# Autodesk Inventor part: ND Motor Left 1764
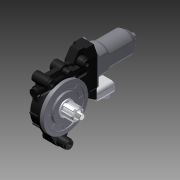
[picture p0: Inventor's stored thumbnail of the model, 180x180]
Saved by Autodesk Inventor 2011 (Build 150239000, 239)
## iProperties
Shininess: 64.0
Length Units: 11269
Angle Units: 11279
Time Units: 11290
Mass Units: 11283
Length Display Precision: 3
Angle Display Precision: 2
Compacted: True
Part Number: ND Motor Left 1764
Document SubType Name: Modeling
Created: 2006-01
Material: ABS Plastic
Designer: uidk0133
Density: 1.06 g/cm^3
Density: 0.0
Volumn: 0.0
Area: 0.0
PropertySet Name: Model Information
Control State: 0
Master: False
Checked Out: False
Author: uidk0133
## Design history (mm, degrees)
sketch "Sketch1"
  geometry: C1 r 36 at (0, 0); 1 further point
  constraints: 1 centre point, 1 coincident, 1 other
  dimensions: "d0" = 72 diameter of C1
extrude "Extrusion1" new body sketch "Sketch1" distance "d1" = 5.8; taper "d2" = 0 deg
sketch "Sketch2"
  geometry: C1 r 36 at (0, 0) reference; C2 r 30 at (0, 0); C3 r 21 at (0, 0)
  constraints: 2 centre point, 2 coincident, 2 concentric
  dimensions: "d3" = 60 diameter of C2; "d4" = 42 diameter of C3
extrude "Extrusion2" cut sketch "Sketch2" distance "d5" = 2; taper "d6" = 0 deg
sketch "Sketch3"
  geometry: C1 r 21 at (0, 0) reference; C2 r 23 at (0, 0); C3 r 21 at (0, 0) reference
  constraints: 1 centre point, 1 concentric
  dimensions: "d7" = 2 radial gap between concentric circles of C2 C1
extrude "Extrusion3" cut sketch "Sketch3" distance "d8" = 1; taper "d9" = 0 deg
sketch "Sketch4"
  geometry: C1 r 21 at (0, 0) reference; C2 r 13 at (0, 0)
  constraints: 1 centre point, 1 coincident, 1 concentric
  dimensions: "d10" = 26 diameter of C2
extrude "Extrusion4" join sketch "Sketch4" distance "d11" = 0.5; taper "d12" = 0 deg
sketch "Sketch5"
  geometry: L1 (0, 30)-(0, 30); L2 (2, 28)-(2, 24); L3 (0, 22)-(0, 22); L4 (-2, 24)-(-2, 28); L5 (0, 0)-(0, 27.01); C1 r 21 at (0, 0) reference; C2 r 23 at (0, 0) reference; A1 r 2 centre (0, 24) between (-2, 24) and (0, 22); A2 r 2 centre (0, 24) between (0, 22) and (2, 24); A3 r 2 centre (0, 28) between (0, 30) and (-2, 28); A4 r 2 centre (0, 28) between (2, 28) and (0, 30); 4 further points
  constraints: 10 end point, 8 point on circle, 8 point on line, 8 tangent, 4 centre point, 3 parallel, 2 concentric, 1 equal radius, 1 horizontal, 1 perpendicular, 1 other
  dimensions: "d13" = 4 distance of point (2, 22) point (-2, 22); "d14" = 8 distance of point (2, 30) point (2, 22); "d15" = 22 vertical distance of C1.centre point (2, 22); "d18" = 2 radius of A1
extrude "Extrusion5" join sketch "Sketch5" distance "d16" = 1.5; taper "d17" = 0 deg
pattern_circular "Circular Pattern1" dims angle "d21" = 360 deg
sketch "Sketch6"
  geometry: C1 r 13 at (0, 0) reference; C2 r 11.95 at (0, 0)
  constraints: 1 centre point, 1 coincident, 1 concentric
  dimensions: "d22" = 23.9 diameter of C2
extrude "Extrusion6" join sketch "Sketch6" distance "d23" = 1.7; taper "d24" = 0 deg
sketch "Sketch7"
  geometry: C1 r 11.95 at (0, 0) reference; C2 r 8.1 at (0, 0)
  constraints: 1 centre point, 1 coincident, 1 concentric
  dimensions: "d25" = 16.2 diameter of C2
extrude "Extrusion7" join sketch "Sketch7" distance "d26" = 17.9; taper "d27" = 0 deg
sketch "Sketch8"
  geometry: C1 r 8.1 at (0, 0) reference; 1 further point
  constraints: 1 coincident
hole "Hole1" sketch "Sketch8" at (0, 0) diameter "d28" = 13; stored, may be unused: countersink angle "d32" = 82 deg, drill point angle "d34" = 0 deg; dims "d29" = 6, "d30" = 4, "d31" = 2, "d33" = 2
sketch "Sketch9"
  geometry: L1 (-2, -7.849)-(2, -7.849); L2 (2, -7.849)-(2, -10); L3 (2, -10)-(-2, -10); L4 (-2, -10)-(-2, -7.849); L5 (0, 0)-(0, 8.1); C1 r 11.95 at (0, 0) reference; A1 r 8.1 centre (0, 0) between (-2, -7.849) and (0, 8.1) reference
  constraints: 10 end point, 3 parallel, 2 point on circle, 1 horizontal, 1 perpendicular, 1 other
  dimensions: "d35" = 4 distance of L2.end L3.end; "d36" = 10 distance from line of L3 A1.centre
extrude "Extrusion8" join sketch "Sketch9" distance "d37" = 18; taper "d38" = 0 deg
chamfer "Chamfer1" distance "d39" = 2; stored, may be unused: second distance "d40" = 2, angle "d354" = 45 deg
pattern_circular "Circular Pattern2" dims angle "d43" = 360 deg
sketch "Sketch10"
  geometry: C1 r 6.5 at (0, 0) reference; C2 r 6.25 at (0, 0)
  constraints: 1 centre point, 1 coincident, 1 concentric
  dimensions: "d44" = 12.5 diameter of C2
extrude "Extrusion9" join sketch "Sketch10" distance "d45" = 0.2; taper "d46" = 0 deg
sketch "Sketch11"
  geometry: C1 r 6.25 at (0, 0) reference; C2 r 4 at (0, 0)
  constraints: 1 centre point, 1 coincident, 1 concentric
  dimensions: "d47" = 8 diameter of C2
extrude "Extrusion10" join sketch "Sketch11" distance "d48" = 8.2; taper "d49" = 0 deg
chamfer "Chamfer2" distance "d50" = 0.5; stored, may be unused: second distance "d51" = 2, angle "d355" = 45 deg
fillet "Fillet1" dims "d52" = 0.5
fillet "Fillet2" dims "d53" = 1.5
sketch "Sketch12"
  geometry: C1 r 36 at (0, 0) reference; C2 r 35.5 at (0, 0)
  constraints: 1 centre point, 1 coincident, 1 concentric
  dimensions: "d54" = 71 diameter of C2
extrude "Extrusion11" join sketch "Sketch12" distance "d55" = 0.5; taper "d56" = 0 deg
sketch "Sketch13"
  geometry: C1 r 36 at (0, 0) reference
extrude "Extrusion12" join sketch "Sketch13" distance "d57" = 3; taper "d58" = 0 deg
sketch "Sketch14"
  geometry: C1 r 36 at (0, 0) reference; C2 r 34 at (0, 0)
  constraints: 1 centre point, 1 coincident, 1 concentric
  dimensions: "d59" = 68 diameter of C2
extrude "Extrusion13" join sketch "Sketch14" distance "d60" = 14; taper "d61" = 0 deg
sketch "Sketch15"
  geometry: L1 (34, -17.5)-(-34, -17.5) reference; L2 (0, -17.5)-(0, -21); L3 (0, -21)-(-10, -21); L4 (-10, -21)-(-32, -17.5)
  constraints: 6 end point, 2 perpendicular, 1 midpoint, 1 point on line
  dimensions: "d62" = 2 distance of L1.end L4.end; "d63" = 3.5 distance of L2.start L2.end; "d64" = 10 distance of L2.end L3.end
revolve "Revolution1" sketch "Sketch15" stored, may be unused: angle "d65" = 90 deg
sketch "Sketch16"
  geometry: L1 (0, 0)-(0, 40.089); L2 (0, 0)-(19.504, 33.782); L3 (1, 9.95)-(1, 31.984); L4 (4.109, 9.117)-(15.126, 28.199); A1 r 10 centre (0, 0) between (1, 9.95) and (4.109, 9.117) reference; A2 r 10 centre (0, 0) between (4.109, 9.117) and (1, 9.95); A3 r 32 centre (0, 0) between (15.126, 28.199) and (1, 31.984); 1 further point
  constraints: 8 end point, 6 point on circle, 2 centre point, 2 coincident, 2 parallel, 1 vertical, 2 other
  dimensions: "d66" = 30 deg angle of L2 L1; "d67" = 1 distance between parallel lines of L1 L3; "d68" = 1 distance between parallel lines of L2 L4
extrude "Extrusion14" cut sketch "Sketch16" distance "d69" = 4.5; taper "d70" = 0 deg
pattern_circular "Circular Pattern3" dims angle "d73" = 360 deg
sketch "Sketch17"
  geometry: C1 r 10 at (0, 0); A1 r 10 centre (0, 0) between (4.109, 9.117) and (1, 9.95) reference; A2 r 10 centre (0, 0) between (8.117, 5.841) and (5.841, 8.117) reference
  constraints: 2 concentric, 1 centre point, 1 coincident
extrude "Extrusion15" join sketch "Sketch17" distance "d74" = 0.5; taper "d75" = 0 deg
fillet "Fillet3" dims "d76" = 0.5
sketch "Sketch18"
  geometry: C1 r 19.5 at (1, -9.95); C2 r 21.5 at (1, -9.95); A1 r 10 centre (1, -9.95) between (0, 0) and (-3.109, -0.833) reference
  constraints: 2 centre point, 1 coincident, 1 concentric
  dimensions: "d77" = 43 diameter of C2; "d78" = 2 radial gap between concentric circles of C1 C2
extrude "Extrusion16" join sketch "Sketch18" distance "d79" = 2; taper "d80" = 0 deg
fillet "Fillet4" dims "d81" = 1
sketch "Sketch19"
  geometry: C1 r 9.5 at (0, 0) reference; 1 further point
  constraints: 1 coincident
hole "Hole2" sketch "Sketch19" at (0, 0) diameter "d82" = 2.6; stored, may be unused: countersink angle "d86" = 82 deg, drill point angle "d88" = 0 deg; dims "d83" = 6, "d84" = 4, "d85" = 2, "d87" = 8
sketch "Sketch21"
  geometry: L1 (-1, 33.985)-(1, 33.985); L2 (1, 33.985)-(1, 35.985); L3 (1, 35.985)-(-1, 35.985); L4 (-1, 35.985)-(-1, 33.985); L5 (-1, 21.477)-(-1, 31.921) reference; L6 (1, 31.921)-(1, 21.477) reference; 1 further point
  constraints: 8 end point, 2 collinear, 2 parallel, 1 horizontal, 1 perpendicular, 2 other
  dimensions: "d93" = 2 distance of L1.end L2.end
extrude "Extrusion18" join sketch "Sketch21" distance "d94" = 15.5; taper "d95" = 0 deg
fillet "Fillet5" dims "d96" = 0.9
pattern_circular "Circular Pattern4" dims angle "d99" = 360 deg
workplane "Work Plane1"
workplane "Work Plane2"
workaxis "Work Axis1"
sketch "Sketch22"
  geometry: L1 (-57.6, -6.2)-(43.2, -6.2) reference; L2 (33.88, -27.93)-(33.88, 48.09) reference; C1 r 7.5 at (33.88, -6.2); 1 further point
  constraints: 2 point on line, 1 centre point, 1 coincident
  dimensions: "d102" = 15 diameter of C1
extrude "Extrusion19" join sketch "Sketch22" distance "d103" = 35; taper "d104" = 0 deg
sketch "Sketch23"
  geometry: C1 r 7.5 at (-33.88, 6.2); 10 further points
  constraints: 1 centre point, 1 coincident, 3 other
extrude "Extrusion20" join sketch "Sketch23" distance "d105" = 20; taper "d106" = 0 deg
sketch "Sketch24"
  geometry: C1 r 11.5 at (-33.88, 6.2); 3 further points
  constraints: 1 centre point, 1 coincident, 2 other
  dimensions: "d110" = 23 diameter of C1
extrude "Extrusion21" join sketch "Sketch24" distance "d108" = 14.5; taper "d109" = 0 deg
sketch "Sketch25"
  geometry: C1 r 7.5 at (0, 0) reference; C2 r 6.125 at (0, 0)
  constraints: 1 centre point, 1 coincident, 1 concentric
  dimensions: "d111" = 12.25 diameter of C2
extrude "Extrusion22" join sketch "Sketch25" distance "d112" = 5; taper "d113" = 0 deg
sketch "Sketch26"
  geometry: L1 (-30, -15.5)-(30, -15.5); L2 (30, -15.5)-(30, 15.5); L3 (30, 15.5)-(-30, 15.5); L4 (-30, 15.5)-(-30, -15.5); L5 (0, 0)-(0, 15.5); L6 (0, 0)-(0, -15.5); L7 (0, 0)-(-30, 0); L8 (0, 0)-(30, 0); C1 r 11.5 at (0, 0) reference
  constraints: 16 end point, 4 midpoint, 4 perpendicular, 3 parallel, 2 collinear, 1 coincident, 1 horizontal, 1 other
  dimensions: "d114" = 60 distance of L2.end L3.end; "d115" = 31 distance of L3.end L1.start
extrude "Extrusion23" join sketch "Sketch26" distance "d116" = 12.5; taper "d117" = 0 deg
fillet "Fillet6" dims "d118" = 4
chamfer "Chamfer3" distance "d119" = 12; stored, may be unused: second distance "d120" = 6, angle "d356" = 45 deg
chamfer "Chamfer4" distance "d121" = 6; stored, may be unused: second distance "d122" = 12, angle "d357" = 45 deg
sketch "Sketch27"
  geometry: L1 (30, 9.5)-(30, -9.5) reference; L2 (18, 15.5)-(30, 9.5) reference; L3 (-26, 15.5)-(18, 15.5) reference; L4 (-30, -11.5)-(-30, 11.5) reference; L5 (18, -15.5)-(-26, -15.5) reference; L6 (30, -9.5)-(18, -15.5) reference; L7 (30, 9.5)-(30, -9.5) reference; L8 (18, 15.5)-(30, 9.5) reference; L9 (17.953, 15.3)-(-26, 15.3); L10 (-29.8, 11.5)-(-29.8, -11.5); L11 (-26, -15.3)-(17.953, -15.3); L12 (17.953, -15.3)-(29.8, -9.376); L13 (29.8, -9.376)-(29.8, -3.693); L14 (23.588, -0.107)-(29.8, -3.693); L15 (30, -9.5)-(18, -15.5) reference; A1 r 4 centre (-26, 11.5) between (-26, 15.5) and (-30, 11.5) reference; A2 r 4 centre (-26, -11.5) between (-30, -11.5) and (-26, -15.5) reference; A3 r 3.8 centre (-26, 11.5) between (-26, 15.3) and (-29.8, 11.5); A4 r 3.8 centre (-26, -11.5) between (-29.8, -11.5) and (-26, -15.3); A5 r 23.588 centre (0, 0) between (23.588, -0.107) and (17.953, 15.3); 1 further point
  constraints: 12 end point, 6 point on circle, 3 centre point, 1 coincident, 1 parallel, 1 other
  dimensions: "d327" = 120 deg angle of L13 L14; "d328" = 0.2 distance between parallel lines of L3 L9; "d329" = 0.2 distance between parallel lines of L15 L12; "d330" = 0.2 distance between parallel lines of L1 L13
extrude "Extrusion24" join sketch "Sketch27" distance "d127" = 2; taper "d128" = 0 deg
fillet "Fillet7" dims "d129" = 1
sketch "Sketch28"
  geometry: L1 (-26, 15.3)-(17.485, 15.3) reference; L2 (17.717, -15.3)-(-26, -15.3) reference; L3 (-12.881, 15.3)-(12.881, 15.3); L4 (-12.881, -15.3)-(12.881, -15.3); A1 r 20 centre (0, 0) between (-12.881, 15.3) and (-12.881, -15.3); A2 r 20 centre (0, 0) between (12.881, -15.3) and (12.881, 15.3); 1 further point
  constraints: 4 end point, 4 point on circle, 4 point on line, 2 centre point, 1 coincident, 1 collinear, 1 concentric, 1 parallel, 1 other
  dimensions: "d332" = 20 radius of A2
extrude "Extrusion25" join sketch "Sketch28" distance "d131" = 15; taper "d132" = 0 deg
sketch "Sketch29"
  geometry: L1 (-12.881, -15.3)-(-12.881, -15.3) reference; L2 (-12.881, 15.3)-(-12.881, 15.3) reference; L3 (12.881, -15.3)-(-12.881, -15.3) reference; L4 (-12.881, 15.3)-(12.881, 15.3) reference; L5 (8.495, -15.3)-(-8.495, -15.3); L6 (8.495, 15.3)-(-8.495, 15.3); A1 r 17.5 centre (0, 0) between (8.495, -15.3) and (8.495, 15.3); A2 r 17.5 centre (0, 0) between (-8.495, 15.3) and (-8.495, -15.3); 1 further point
  constraints: 4 end point, 4 point on circle, 4 point on line, 2 centre point, 1 coincident, 1 concentric, 1 other
  dimensions: "d334" = 17.5 radius of A2
extrude "Extrusion26" join sketch "Sketch29" distance "d135" = 40; taper "d136" = 0 deg
chamfer "Chamfer5" distance "d137" = 2.5; stored, may be unused: second distance "d138" = 12, angle "d358" = 45 deg
chamfer "Chamfer6" distance "d139" = 1; stored, may be unused: second distance "d140" = 12, angle "d359" = 45 deg
fillet "Fillet8" dims "d143" = 4
sketch "Sketch31"
  geometry: L1 (-7.386, -15.3)-(7.386, -15.3); L2 (7.386, 15.3)-(-7.386, 15.3) reference; A1 r 4 centre (7.386, -11.3) between (7.386, -15.3) and (9.575, -14.648); A2 r 4 centre (-7.386, -11.3) between (-9.575, -14.648) and (-7.386, -15.3); A3 r 17.5 centre (0, 0) between (-9.575, -14.648) and (9.575, -14.648); A4 r 4 centre (7.386, 11.3) between (9.575, 14.648) and (7.386, 15.3) reference; A5 r 17.5 centre (0, 0) between (9.575, 14.648) and (-9.575, 14.648) reference; A6 r 4 centre (-7.386, 11.3) between (-7.386, 15.3) and (-9.575, 14.648) reference
  constraints: 6 point on circle, 3 centre point, 2 end point
extrude "Extrusion27" cut sketch "Sketch31" stored distance "d145" = 43; taper "d146" = 0 deg
mirror "Mirror1"
sketch "Sketch32"
  geometry: C1 r 9.896 at (0, 0); C2 r 5 at (0, 0); C3 r 12 at (0, 0) reference
  constraints: 2 centre point, 1 coincident, 1 concentric
  dimensions: "d150" = 10 diameter of C2
extrude "Extrusion28" join sketch "Sketch32" distance "d151" = 4; taper "d152" = 0 deg
sketch "Sketch33"
  geometry: C1 r 5 at (0, 0) reference; C2 r 4.5 at (0, 0)
  constraints: 1 centre point, 1 coincident, 1 concentric
  dimensions: "d153" = 9 diameter of C2
extrude "Extrusion29" join sketch "Sketch33" distance "d154" = 5; taper "d155" = 0 deg
fillet "Fillet10" dims "d156" = 1, "d157" = 0.5
sketch "Sketch35"
  geometry: L1 (-22.38, 25.596)-(-22.38, 34.5) reference; L2 (-3.88, 34.5)-(-7.88, 34.5) reference; L3 (-22.38, 25.596)-(-22.38, 34.5); L4 (-3.88, 34.5)-(-3.88, 33.778); L5 (-7.88, 34.5)-(-22.38, 34.5); A1 r 34 centre (0, 0) between (-0.1, 34) and (-16.913, 29.495) reference; A2 r 34 centre (0, 0) between (-17.087, 29.395) and (-29.395, 17.087) reference; A3 r 34 centre (0, 0) between (-3.88, 33.778) and (-22.38, 25.596); 3 further points
  constraints: 6 end point, 3 point on circle, 1 centre point, 1 coincident, 1 collinear, 1 parallel, 1 perpendicular
extrude "Extrusion30" join sketch "Sketch35" stored distance "d158" = 2; taper "d159" = 0 deg
sketch "Sketch36"
  geometry: L1 (-30, -9.5)-(-30, 9.5); L2 (-30, 6.6)-(0, 6.6); L3 (0, 6.6)-(0, -6.6); L4 (0, -6.6)-(-30, -6.6); L5 (-30, -6.6)-(-30, 6.6); L6 (0, 0)-(-24.292, 0); L7 (30, -1)-(11.5, -1) reference; L8 (11.5, -1)-(11.5, 0) reference; L9 (11.5, 0)-(11.5, 1) reference; L10 (11.5, 1)-(30, 1) reference; L11 (30, 2.7)-(30, 1) reference; L12 (23.597, 2.7)-(30, 2.7) reference; L13 (23.597, 5.7)-(23.597, 2.7) reference; L14 (25.513, 5.7)-(23.597, 5.7) reference; L15 (25.513, 6.2)-(25.513, 5.7) reference; L16 (23.597, 6.2)-(25.513, 6.2) reference; L17 (23.597, 11.5)-(23.597, 6.2) reference; L18 (30, 12)-(25.513, 12) reference; L19 (30, 15.5)-(30, 12) reference; L20 (23.717, 15.5)-(30, 15.5) reference; L21 (-30, -11.5)-(-30, 11.5) reference; L22 (18, -15.5)-(-26, -15.5) reference; L23 (30, -9.5)-(18, -15.5) reference; L24 (30, -1)-(30, -9.5) reference; C1 r 11.5 at (0, 0); C2 r 11.5 at (0, 0) reference; A1 r 4 centre (-26, 11.5) between (-26, 15.5) and (-30, 11.5) reference; A2 r 4 centre (-26, -11.5) between (-30, -11.5) and (-26, -15.5) reference
  constraints: 12 end point, 2 parallel, 2 perpendicular, 1 centre point, 1 horizontal, 1 point on line, 2 other
  dimensions: "d160" = 13.2 distance of L2.end L3.end; "d161" = 30 distance of L3.end L4.end
extrude "Extrusion31" join sketch "Sketch36" distance "d162" = 18; taper "d163" = 0 deg
chamfer "Chamfer8" distance "d164" = 9; stored, may be unused: second distance "d165" = 14, angle "d360" = 45 deg
sketch "Sketch37"
  geometry: L1 (-16, -6.6)-(-16, 6.6) reference; L2 (-6.537, 3.677)-(-16, 3.677); L3 (-16, 3.677)-(-16, -3.323); L4 (-16, -3.323)-(-6.537, -3.323); L5 (-6.537, -3.323)-(-6.537, 3.677); L6 (-1.408, 0)-(-40.663, 0); A1 r 7.5 centre (0, 0) between (-3.562, 6.6) and (-3.562, -6.6) reference; A2 r 7.333 centre (0, 0) between (-6.391, 3.595) and (-6.537, -3.323); 1 further point
  constraints: 10 end point, 3 point on circle, 2 coincident, 2 parallel, 2 perpendicular, 1 centre point, 1 collinear, 1 horizontal, 1 other
  dimensions: "d166" = 7 distance of L2.end L3.end
extrude "Extrusion32" join sketch "Sketch37" distance "d167" = 50; taper "d168" = 0 deg
sketch "Sketch38"
  geometry: L1 (59.3, -14.5)-(54.081, -14.5); L2 (5.917, 14.5)-(0.7, 14.5) reference; L3 (0, 0)-(0, -9) reference; C1 r 7 at (14.88, -6.21)
  constraints: 2 end point, 1 centre point
  dimensions: "d170" = 14 diameter of C1; "d337" = 20.71 distance from line of C1.centre L2; "d353" = 14.88 distance from line of C1.centre L3
extrude "Extrusion33" join sketch "Sketch38" distance "d172" = 8.2; taper "d173" = 0 deg
sketch "Sketch39"
  geometry: C1 r 6.15 at (14.88, -6.21); A1 r 7 centre (14.88, -6.21) between (11.65, 0) and (18.11, 0) reference
  constraints: 1 centre point, 1 coincident, 1 concentric
  dimensions: "d174" = 12.3 diameter of C1
extrude "Extrusion34" join sketch "Sketch39" distance "d175" = 3; taper "d176" = 0 deg
sketch "Sketch40"
  geometry: C1 r 6.15 at (0, 0) reference; 1 further point
  constraints: 1 coincident
hole "Hole3" sketch "Sketch40" at (0, 0) diameter "d177" = 4.8; stored, may be unused: countersink angle "d181" = 82 deg, drill point angle "d183" = 0 deg; dims "d178" = 6, "d179" = 6.2, "d180" = 2, "d182" = 8
sketch "Sketch41"
  geometry: L1 (-26.38, -35)-(-41.38, -35) reference; L2 (-26.38, -21.45)-(-26.38, -35) reference; L3 (-26.38, -35)-(-22.38, -35); L4 (-22.38, -35)-(-17.481, -29.162); L5 (-26.38, -21.45)-(-26.38, -35); A1 r 34 centre (0, 0) between (-16.913, -29.495) and (-0.1, -34) reference; A2 r 34 centre (0, 0) between (-29.395, -17.087) and (-17.087, -29.395) reference; A3 r 34 centre (0, 0) between (-26.38, -21.45) and (-17.481, -29.162); 1 further point
  constraints: 6 end point, 3 point on circle, 1 centre point, 1 coincident, 1 collinear, 1 perpendicular
  dimensions: "d314" = 4 distance of L2.end L3.end; "d315" = 130 deg angle of L3 L4
extrude "Extrusion35" join sketch "Sketch41" stored distance "d186" = 2; taper "d187" = 0 deg
sketch "Sketch43"
  geometry: L1 (-22.38, -35)-(-18.526, -30.407) reference; L2 (-15.704, -30.156)-(-21.447, -37); L3 (-21.447, -37)-(-33.88, -37); L4 (-22.38, -35)-(-17.481, -29.162); L5 (-22.38, -35)-(-33.88, -35); L6 (-26.38, -35)-(-41.38, -35) reference; L7 (-33.88, -35)-(-33.88, -37); L8 (-33.88, -35)-(-33.88, -37); A1 r 34 centre (0, 0) between (-16.913, -29.495) and (-0.1, -34) reference; A2 r 34 centre (0, 0) between (-29.395, -17.087) and (-17.087, -29.395) reference; A3 r 34 centre (0, 0) between (-17.087, -29.395) and (-15.704, -30.156); 1 further point
  constraints: 12 end point, 4 point on circle, 1 centre point, 1 coincident, 1 collinear, 1 midpoint, 1 parallel, 1 perpendicular, 1 point on line
  dimensions: "d317" = 2 distance between parallel lines of L2 L1; "d318" = 2 distance from line of L3 L6.start
extrude "Extrusion36" join sketch "Sketch43" stored distance "d191" = 7; taper "d192" = 0 deg
sketch "Sketch46"
  geometry: L1 (-43.896, 112)-(-24.104, 112) reference; C1 r 7 at (-49, -28.29); C2 r 3.1 at (-49, 28.29) reference; A1 r 7 centre (-49, 28.29) between (-52.23, 34.5) and (-45.77, 34.5) reference
  constraints: 1 centre point, 1 equal radius, 1 vertical alignment
  dimensions: "d320" = 56.58 distance of C1.centre A1.centre
extrude "Extrusion39" join sketch "Sketch46" distance "d200" = 14.8; taper "d201" = 0 deg
sketch "Sketch47"
  geometry: C1 r 7 at (0, 0) reference; C2 r 6.15 at (0, 0)
  constraints: 1 centre point, 1 coincident, 1 concentric
  dimensions: "d202" = 12.3 diameter of C2
extrude "Extrusion40" join sketch "Sketch47" distance "d203" = 3; taper "d204" = 0 deg
sketch "Sketch48"
  geometry: C1 r 7 at (49, -28.29); 3 further points
  constraints: 1 centre point, 1 coincident, 2 other
extrude "Extrusion41" join sketch "Sketch48" distance "d205" = 8; taper "d206" = 0 deg
sketch "Sketch49"
  geometry: C1 r 6.15 at (0, 0) reference; 1 further point
  constraints: 1 coincident
hole "Hole4" sketch "Sketch49" at (0, 0) diameter "d207" = 4.8; stored, may be unused: countersink angle "d211" = 82 deg, drill point angle "d213" = 0 deg; dims "d208" = 6, "d209" = 6.2, "d210" = 2, "d212" = 8
sketch "Sketch50"
  geometry: L1 (0, 0)-(0, 38.5); L2 (0, 0)-(0, -37.846) reference; L3 (33.485, 30.5)-(-10, 30.5) reference; C1 r 7.75 at (5, -10.5)
  constraints: 2 end point, 1 centre point
  dimensions: "d214" = 15.5 diameter of C1; "d321" = 41 distance from line of L3 C1.centre; "d322" = 5 distance from line of L2 C1.centre
extrude "Extrusion42" join sketch "Sketch50" distance "d217" = 16; taper "d218" = 0 deg
sketch "Sketch51"
  geometry: L1 (10.116, 18)-(9.271, -14.855); L2 (0, 0)-(0, -4.579) reference; L3 (5.861, -14.662)-(9.457, -14.866); L4 (3.213, -6.644)-(4.612, 18); L5 (9.457, -14.866)-(9.47, 18); L6 (6.582, 18)-(27.5, 18) reference; L7 (4.11, 18)-(6.582, 18) reference; L8 (9.47, 18)-(4.11, 18); A1 r 7.75 centre (5, -10.5) between (0, -4.579) and (0, -16.421) reference; A2 r 4.25 centre (5, -10.5) between (3.213, -6.644) and (5.861, -14.662); 1 further point
  constraints: 10 end point, 5 point on line, 2 point on circle, 1 centre point, 1 coincident, 1 collinear, 1 concentric, 1 perpendicular
  dimensions: "d324" = 3.5 radial gap between concentric circles of A1 A2
extrude "Extrusion43" join sketch "Sketch51" distance "d222" = 9.5; taper "d223" = 0 deg
sketch "Sketch54"
  geometry: C1 r 7.1 at (48.4, 0); 1 further point
  constraints: 1 centre point, 1 horizontal alignment, 1 other
  dimensions: "d230" = 14.2 diameter of C1; "d231" = 48.4 distance of C1.centre point (0, 0)
extrude "Extrusion46" join sketch "Sketch54" distance "d232" = 14.8; taper "d233" = 0 deg
sketch "Sketch55"
  geometry: C1 r 7.1 at (0, 0) reference; C2 r 6.15 at (0, 0)
  constraints: 1 centre point, 1 coincident, 1 concentric
  dimensions: "d234" = 12.3 diameter of C2
extrude "Extrusion47" join sketch "Sketch55" distance "d235" = 3; taper "d236" = 0 deg
sketch "Sketch56"
  geometry: C1 r 7.1 at (0, 0) reference; C2 r 8.25 at (0, 0)
  constraints: 1 centre point, 1 coincident, 1 concentric
  dimensions: "d237" = 16.5 diameter of C2
extrude "Extrusion48" join sketch "Sketch56" distance "d238" = 17.5; taper "d239" = 0 deg
sketch "Sketch57"
  geometry: C1 r 6.15 at (0, 0) reference; 1 further point
  constraints: 1 coincident
hole "Hole5" sketch "Sketch57" at (0, 0) diameter "d240" = 4.8; stored, may be unused: countersink angle "d244" = 82 deg, drill point angle "d246" = 118 deg; dims "d241" = 6, "d242" = 6.2, "d243" = 2, "d245" = 28
sketch "Sketch58"
  geometry: C1 r 8.25 at (0, 0) reference; 1 further point
  constraints: 1 coincident
hole "Hole6" sketch "Sketch58" at (0, 0) diameter "d247" = 4.134; stored, may be unused: countersink angle "d251" = 82 deg, drill point angle "d253" = 0 deg; dims "d248" = 6, "d249" = 4.9, "d250" = 2, "d252" = 8
sketch "Sketch60"
  geometry: L1 (-31.114, -18.079)-(-31.214, -17.906) reference; L2 (-30.885, -16.677)-(-29.932, -16.127) reference; L3 (-33.985, -1)-(-35.085, -1) reference; L4 (-35.985, -0.1)-(-35.985, 0.1) reference; L5 (-35.085, 1)-(-33.985, 1) reference; L6 (-29.932, 16.127)-(-30.885, 16.677) reference; L7 (-31.214, 17.906)-(-31.114, 18.079) reference; L8 (-28.932, 17.859)-(-29.885, 18.409) reference; L9 (-29.885, -18.409)-(-28.932, -17.859) reference; L10 (-30.749, 18.428)-(-52.193, 7.326); L11 (-52.193, -7.326)-(-30.749, -18.428); L12 (-28.932, -17.859)-(-29.885, -18.409); A1 r 0.9 centre (-30.335, -17.629) between (-31.114, -18.079) and (-29.885, -18.409) reference; A2 r 0.9 centre (-30.435, -17.456) between (-30.885, -16.677) and (-31.214, -17.906) reference; A3 r 34 centre (0, 0) between (-33.985, -1) and (-29.932, -16.127) reference; A4 r 0.9 centre (-35.085, -0.1) between (-35.985, -0.1) and (-35.085, -1) reference; A5 r 0.9 centre (-35.085, 0.1) between (-35.085, 1) and (-35.985, 0.1) reference; A6 r 34 centre (0, 0) between (-29.932, 16.127) and (-33.985, 1) reference; A7 r 0.9 centre (-30.435, 17.456) between (-31.214, 17.906) and (-30.885, 16.677) reference; A8 r 0.9 centre (-30.335, 17.629) between (-29.885, 18.409) and (-31.114, 18.079) reference; A9 r 8.25 centre (-48.4, 0) between (-52.193, 7.326) and (-52.193, -7.326) reference; A10 r 34 centre (0, 0) between (-29.495, 16.913) and (-34, 0.1) reference; A11 r 34 centre (0, 0) between (-34, -0.1) and (-29.495, -16.913) reference; A12 r 0.9 centre (-30.335, 17.629) between (-29.885, 18.409) and (-31.114, 18.079) reference; A13 r 0.9 centre (-30.335, -17.629) between (-31.114, -18.079) and (-29.885, -18.409) reference; A14 r 8.25 centre (-48.4, 0) between (-52.193, -7.326) and (-52.193, 7.326); A15 r 0.9 centre (-30.335, 17.629) between (-29.885, 18.409) and (-30.749, 18.428); A16 r 34 centre (0, 0) between (-28.932, 17.859) and (-28.932, -17.859); A17 r 0.9 centre (-30.335, -17.629) between (-30.513, -18.511) and (-29.885, -18.409)
  constraints: 14 point on circle, 6 end point, 6 tangent, 4 centre point, 4 coincident, 1 collinear
extrude "Extrusion50" join sketch "Sketch60" stored distance "d259" = 2; taper "d260" = 0 deg
sketch "Sketch61"
  geometry: C1 r 8.25 at (0, 0) reference; C2 r 7.1 at (0, 0) reference
extrude "Extrusion51" join sketch "Sketch61" stored distance "d261" = 2; taper "d262" = 0 deg
sketch "Sketch63"
  geometry: L1 (-30.749, -18.428)-(-52.193, -7.326) reference; L2 (-31.214, -17.906)-(-31.114, -18.079) reference; L3 (-29.932, -16.127)-(-30.885, -16.677) reference; L4 (-35.085, -1)-(-33.985, -1) reference; L5 (-35.985, 0.1)-(-35.985, -0.1) reference; L6 (-33.985, 1)-(-35.085, 1) reference; L7 (-30.885, 16.677)-(-29.932, 16.127) reference; L8 (-31.114, 18.079)-(-31.214, 17.906) reference; L9 (-52.193, 7.326)-(-30.749, 18.428) reference; A1 r 0.9 centre (-30.335, -17.629) between (-31.114, -18.079) and (-30.749, -18.428) reference; A2 r 0.9 centre (-30.435, -17.456) between (-30.885, -16.677) and (-31.214, -17.906) reference; A3 r 34 centre (0, 0) between (-33.985, -1) and (-29.932, -16.127) reference; A4 r 0.9 centre (-35.085, -0.1) between (-35.985, -0.1) and (-35.085, -1) reference; A5 r 0.9 centre (-35.085, 0.1) between (-35.085, 1) and (-35.985, 0.1) reference; A6 r 34 centre (0, 0) between (-29.932, 16.127) and (-33.985, 1) reference; A7 r 0.9 centre (-30.435, 17.456) between (-31.214, 17.906) and (-30.885, 16.677) reference; A8 r 0.9 centre (-30.335, 17.629) between (-30.749, 18.428) and (-31.114, 18.079) reference; A9 r 8.25 centre (-48.4, 0) between (-52.193, -7.326) and (-52.193, 7.326) reference
extrude "Extrusion52" join sketch "Sketch63" distance "d263" = 13; taper "d264" = 0 deg
sketch "Sketch66"
  geometry: L1 (-0.8, 86.5)-(6.2, 86.5) reference; L2 (2.7, 86.5)-(2.7, 98.17); L3 (-6.8, 2)-(12.2, 2); L4 (12.2, 2)-(12.2, 17); L5 (12.2, 17)-(-6.8, 17); L6 (-6.8, 17)-(-6.8, 2); L7 (18.2, 0)-(14.2, 0) reference
  constraints: 10 end point, 2 parallel, 2 perpendicular, 1 horizontal, 1 midpoint, 1 other
  dimensions: "d338" = 2 distance between parallel lines of L7 L3; "d339" = 15 distance of L3.end L4.end; "d340" = 19 distance of L4.end L5.end
extrude "Extrusion53" join sketch "Sketch66" distance "d270" = 18.5; taper "d271" = 0 deg
chamfer "Chamfer9" distance "d272" = 9; stored, may be unused: second distance "d273" = 13, angle "d361" = 45 deg
sketch "Sketch68"
  geometry: L1 (0, 19)-(0, 0) reference; L2 (23, -2)-(7.5, -2); L3 (7.5, -2)-(7.5, 21); L4 (7.5, 21)-(23, 21); L5 (23, 21)-(23, -2); L6 (-30, 9.5)-(-66.817, 9.5); C1 r 3.5 at (-30, 9.5) reference
  constraints: 10 end point, 2 parallel, 2 perpendicular, 1 horizontal, 1 other
  dimensions: "d345" = 7.5 distance between parallel lines of L1 L3; "d346" = 15.5 distance between parallel lines of L5 L3; "d347" = 23 distance between parallel lines of L4 L2
extrude "Extrusion55" join sketch "Sketch68" distance "d287" = 27.3; taper "d288" = 0 deg
fillet "Fillet12" dims "d289" = 5
sketch "Sketch69"
  geometry: L1 (7.5, 3)-(7.5, 16); L2 (18, -2)-(12.5, -2); L3 (23, 16)-(23, 3); L4 (12.5, 21)-(18, 21); L5 (12.5, 19.4)-(18, 19.4); L6 (21.4, 16)-(21.4, 3); L7 (18, -0.4)-(12.5, -0.4); L8 (9.1, 3)-(9.1, 16); L9 (12.5, 21)-(18, 21) reference; L10 (7.5, 3)-(7.5, 16) reference; L11 (18, -2)-(12.5, -2) reference; L12 (23, 16)-(23, 3) reference; A1 r 5 centre (12.5, 16) between (12.5, 21) and (7.5, 16); A2 r 5 centre (12.5, 3) between (7.5, 3) and (12.5, -2); A3 r 5 centre (18, 3) between (18, -2) and (23, 3); A4 r 5 centre (18, 16) between (23, 16) and (18, 21); A5 r 3.4 centre (12.5, 16) between (12.5, 19.4) and (9.1, 16); A6 r 3.4 centre (18, 16) between (21.4, 16) and (18, 19.4); A7 r 3.4 centre (18, 3) between (18, -0.4) and (21.4, 3); A8 r 3.4 centre (12.5, 3) between (9.1, 3) and (12.5, -0.4); A9 r 5 centre (18, 16) between (23, 16) and (18, 21) reference; A10 r 5 centre (12.5, 16) between (12.5, 21) and (7.5, 16) reference; A11 r 5 centre (12.5, 3) between (7.5, 3) and (12.5, -2) reference; A12 r 5 centre (18, 3) between (18, -2) and (23, 3) reference
  constraints: 16 end point, 16 point on circle, 8 centre point, 7 other
  dimensions: "d290" = 1.6 distance between parallel lines of L4 L5
extrude "Extrusion56" cut sketch "Sketch69" distance "d291" = 24.3; taper "d292" = 0 deg
sketch "Sketch70"
  geometry: L1 (0, 0)-(0, 27.3) reference; L2 (13, 27.3)-(13, 0) reference; L3 (0, 24.3)-(13, 24.3); L4 (13, 24.3)-(13, 10.5); L5 (13, 10.5)-(0, 10.5); L6 (0, 10.5)-(0, 24.3); L7 (13, 27.3)-(0, 27.3) reference
  constraints: 8 end point, 2 parallel, 2 point on line, 1 horizontal, 1 perpendicular
  dimensions: "d348" = 3 distance between parallel lines of L7 L3; "d349" = 13.8 distance between parallel lines of L5 L3
extrude "Extrusion57" join sketch "Sketch70" distance "d295" = 7; taper "d296" = 0 deg
chamfer "Chamfer10" distance "d302" = 5; stored, may be unused: second distance "d303" = 10, angle "d362" = 45 deg
sketch "Sketch72"
  geometry: L1 (7, 0)-(7, 13); L2 (0, 0)-(0, 13); L3 (0, 11)-(5, 11); L4 (5, 11)-(5, 2); L5 (5, 2)-(0, 2); L6 (0, 2)-(0, 11); L7 (-53, 6.5)-(-108.601, 6.5); L8 (7, 0)-(7, 13) reference; L9 (0, 13)-(7, 13) reference; L10 (0, 0)-(0, 13) reference; L11 (0, 0)-(7, 0) reference; C1 r 9.896 at (-53, 6.5)
  constraints: 14 end point, 2 parallel, 2 perpendicular, 1 centre point, 1 horizontal, 1 point on line, 1 other
  dimensions: "d304" = 9 distance between parallel lines of L5 L3; "d305" = 2 distance between parallel lines of L1 L4
extrude "Extrusion59" cut sketch "Sketch72" distance "d306" = 12.5; taper "d307" = 0 deg
body "Solid1"
revolve "Revolution2" stored, may be unused: angle "d352" = 90 deg
node "Projected Loop3"
sketch "Sketch30"
  geometry: L1 (-26.494, 104)-(-41.266, 104); L2 (-51.38, 104)-(-43.455, 104); L3 (-51.38, 104)-(-33.88, 104); L4 (-33.88, 104)-(-33.88, 112); L5 (-33.88, 112)-(-45.88, 112); L6 (-45.88, 112)-(-51.38, 104)
  constraints: 12 end point, 2 perpendicular, 1 midpoint
  dimensions: "d350" = 8 distance of L3.end L4.end; "d351" = 12 distance of L4.end L5.end
other parameters: "d100" = -12, "d101" = -33.88, "d133" = 35, "d219" = 9, "d333" = 34.3402
